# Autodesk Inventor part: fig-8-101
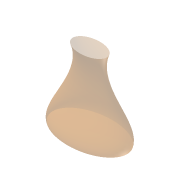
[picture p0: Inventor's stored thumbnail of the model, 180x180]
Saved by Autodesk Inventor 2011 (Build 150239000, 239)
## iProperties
Created: 2004-05
Part Number: fig-8-101
Document SubType Name: Modeling
Designer: CADCIM Technologies
Manufacturer: Standard
Standards Organization: Custom
Density: 1 g/cm^3
Author: CADCIM Technologies
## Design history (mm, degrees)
sketch "Sketch4"
  geometry: 1 further point; 1 other entity
  constraints: 2 other
workplane "Work Plane2"
sketch "Sketch5"
  geometry: 1 further point; 1 other entity
  constraints: 2 other
feature "LoftSrf1" sketch "Sketch5" dims "d4" = 20, "d5" = 110 deg, "d6" = 40, "d7" = 70 deg
patch "Boundary Patch1" dims "d8" = 0, "d9" = 0
body "Srf1"
body "Srf2"
other parameters: "d3" = 33.5
